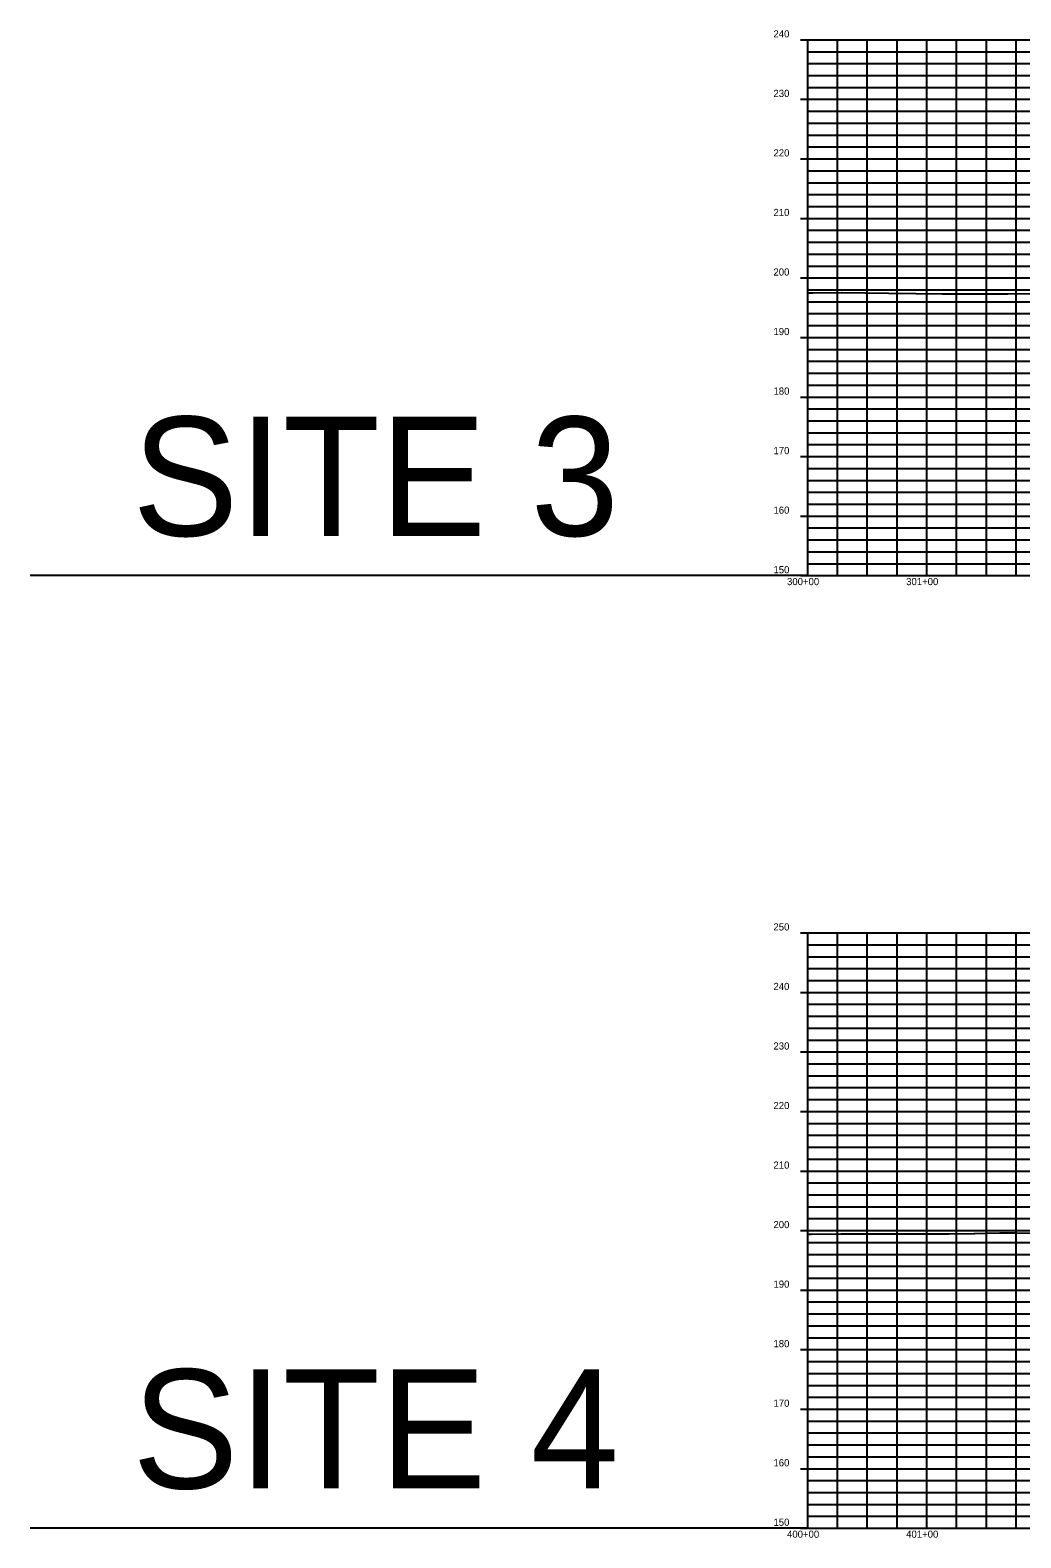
# Model space of a CAD drawing. Extents: x 1399671 to 1408349, y 1930471 to 1933387.
# Drawn here: x 1399671 to 1400503, y 1930471 to 1931737 of the extents above; entities that cross this region are included whole.
import ezdxf

# ---------------------------------------------------------------- set-up
doc = ezdxf.new("R2010")
doc.units = 0
for name, color, linetype in [('63', 7, 'Continuous'), ('8', 7, 'Continuous'), ('R_Exist Surface', 7, 'Continuous'), ('R_Grid', 7, 'Continuous'), ('R_Grid Annot', 7, 'Continuous')]:
    doc.layers.add(name, color=color, linetype=linetype)

msp = doc.modelspace()

# ---------------------------------------------------------------- linework, layer by layer
at = {"layer": '8'}
for p, q in [((1400324.2, 1931278.6), (1399671.4, 1931278.6)), ((1400324.2, 1930478.6), (1399671.4, 1930478.6))]:
    msp.add_line(p, q, dxfattribs=at)
at = {"layer": 'R_Exist Surface'}
for points in [[(1400324.2, 1931516.2), (1400328.2, 1931516.2), (1400328.8, 1931516.2), (1400352.6, 1931516.4), (1400353, 1931516.4), (1400372.3, 1931516.1), (1400372.5, 1931516.1), (1400372.8, 1931516.1), (1400392.1, 1931515.8), (1400392.3, 1931515.8), (1400414.9, 1931515.5), (1400437.1, 1931515.3), (1400437.8, 1931515.3), (1400451, 1931515.3), (1400451.4, 1931515.3), (1400464.6, 1931515.3), (1400464.9, 1931515.3), (1400478.2, 1931515.3), (1400478.5, 1931515.3), (1400478.7, 1931515.3), (1400492.1, 1931515.3), (1400492.3, 1931515.3), (1400516.2, 1931515.6)], [(1400324.2, 1930725.6), (1400324.4, 1930725.6), (1400327.1, 1930725.6), (1400327.1, 1930725.6), (1400351.9, 1930725.7), (1400352, 1930725.7), (1400352.1, 1930725.7), (1400376.7, 1930725.7), (1400376.9, 1930725.7), (1400377.2, 1930725.7), (1400393.4, 1930725.7), (1400393.8, 1930725.7), (1400409.8, 1930725.8), (1400425.7, 1930725.8), (1400426.3, 1930725.8), (1400442.1, 1930725.9), (1400442.8, 1930725.9), (1400463.6, 1930726.2), (1400464.1, 1930726.2), (1400464.6, 1930726.2), (1400485.5, 1930726.6), (1400485.6, 1930726.6), (1400495.2, 1930726.6), (1400498.3, 1930726.6), (1400511.1, 1930726.5)]]:
    msp.add_lwpolyline(points, dxfattribs=at)
at = {"layer": 'R_Grid'}
for p, q in [((1400324.2, 1931278.6), (1400324.2, 1931728.6)), ((1400324.2, 1931728.6), (1408324.2, 1931728.6)), ((1400324.2, 1931728.6), (1408324.2, 1931728.6)), ((1400349.2, 1931278.6), (1400349.2, 1931728.6)), ((1400374.2, 1931278.6), (1400374.2, 1931728.6)), ((1400399.2, 1931278.6), (1400399.2, 1931728.6)), ((1400424.2, 1931278.6), (1400424.2, 1931728.6)), ((1400449.2, 1931278.6), (1400449.2, 1931728.6)), ((1400474.2, 1931278.6), (1400474.2, 1931728.6)), ((1400499.2, 1931278.6), (1400499.2, 1931728.6)), ((1400324.2, 1931718.6), (1408324.2, 1931718.6)), ((1400324.2, 1931708.6), (1408324.2, 1931708.6)), ((1400324.2, 1931698.6), (1408324.2, 1931698.6)), ((1400324.2, 1931688.6), (1408324.2, 1931688.6)), ((1400324.2, 1931678.6), (1408324.2, 1931678.6)), ((1400324.2, 1931668.6), (1408324.2, 1931668.6)), ((1400324.2, 1931658.6), (1408324.2, 1931658.6)), ((1400324.2, 1931648.6), (1408324.2, 1931648.6)), ((1400324.2, 1931638.6), (1408324.2, 1931638.6)), ((1400324.2, 1931628.6), (1408324.2, 1931628.6)), ((1400324.2, 1931618.6), (1408324.2, 1931618.6)), ((1400324.2, 1931608.6), (1408324.2, 1931608.6)), ((1400324.2, 1931598.6), (1408324.2, 1931598.6)), ((1400324.2, 1931588.6), (1408324.2, 1931588.6)), ((1400324.2, 1931578.6), (1408324.2, 1931578.6)), ((1400324.2, 1931568.6), (1408324.2, 1931568.6)), ((1400324.2, 1931558.6), (1408324.2, 1931558.6)), ((1400324.2, 1931548.6), (1408324.2, 1931548.6)), ((1400324.2, 1931538.6), (1408324.2, 1931538.6)), ((1400324.2, 1931528.6), (1408324.2, 1931528.6)), ((1400324.2, 1931518.6), (1408324.2, 1931518.6)), ((1400324.2, 1931508.6), (1408324.2, 1931508.6)), ((1400324.2, 1931498.6), (1408324.2, 1931498.6)), ((1400324.2, 1931488.6), (1408324.2, 1931488.6)), ((1400324.2, 1931478.6), (1408324.2, 1931478.6)), ((1400324.2, 1931468.6), (1408324.2, 1931468.6)), ((1400324.2, 1931458.6), (1408324.2, 1931458.6)), ((1400324.2, 1931448.6), (1408324.2, 1931448.6)), ((1400324.2, 1931438.6), (1408324.2, 1931438.6)), ((1400324.2, 1931428.6), (1408324.2, 1931428.6)), ((1400324.2, 1931418.6), (1408324.2, 1931418.6)), ((1400324.2, 1931408.6), (1408324.2, 1931408.6)), ((1400324.2, 1931398.6), (1408324.2, 1931398.6)), ((1400324.2, 1931388.6), (1408324.2, 1931388.6)), ((1400324.2, 1931378.6), (1408324.2, 1931378.6)), ((1400324.2, 1931368.6), (1408324.2, 1931368.6)), ((1400324.2, 1931358.6), (1408324.2, 1931358.6)), ((1400324.2, 1931348.6), (1408324.2, 1931348.6)), ((1400324.2, 1931338.6), (1408324.2, 1931338.6)), ((1400324.2, 1931328.6), (1408324.2, 1931328.6)), ((1400324.2, 1931318.6), (1408324.2, 1931318.6)), ((1400324.2, 1931308.6), (1408324.2, 1931308.6)), ((1400324.2, 1931298.6), (1408324.2, 1931298.6)), ((1400324.2, 1931288.6), (1408324.2, 1931288.6)), ((1400324.2, 1931278.6), (1408324.2, 1931278.6)), ((1400324.2, 1930478.6), (1400324.2, 1930978.6)), ((1400324.2, 1930978.6), (1407124.2, 1930978.6)), ((1400324.2, 1930978.6), (1407124.2, 1930978.6)), ((1400324.2, 1930968.6), (1407124.2, 1930968.6)), ((1400349.2, 1930478.6), (1400349.2, 1930978.6)), ((1400374.2, 1930478.6), (1400374.2, 1930978.6)), ((1400399.2, 1930478.6), (1400399.2, 1930978.6)), ((1400424.2, 1930478.6), (1400424.2, 1930978.6)), ((1400449.2, 1930478.6), (1400449.2, 1930978.6)), ((1400474.2, 1930478.6), (1400474.2, 1930978.6)), ((1400499.2, 1930478.6), (1400499.2, 1930978.6)), ((1400324.2, 1930958.6), (1407124.2, 1930958.6)), ((1400324.2, 1930948.6), (1407124.2, 1930948.6)), ((1400324.2, 1930938.6), (1407124.2, 1930938.6)), ((1400324.2, 1930928.6), (1407124.2, 1930928.6)), ((1400324.2, 1930918.6), (1407124.2, 1930918.6)), ((1400324.2, 1930908.6), (1407124.2, 1930908.6)), ((1400324.2, 1930898.6), (1407124.2, 1930898.6)), ((1400324.2, 1930888.6), (1407124.2, 1930888.6)), ((1400324.2, 1930878.6), (1407124.2, 1930878.6)), ((1400324.2, 1930868.6), (1407124.2, 1930868.6)), ((1400324.2, 1930858.6), (1407124.2, 1930858.6)), ((1400324.2, 1930848.6), (1407124.2, 1930848.6)), ((1400324.2, 1930838.6), (1407124.2, 1930838.6)), ((1400324.2, 1930828.6), (1407124.2, 1930828.6)), ((1400324.2, 1930818.6), (1407124.2, 1930818.6)), ((1400324.2, 1930808.6), (1407124.2, 1930808.6)), ((1400324.2, 1930798.6), (1407124.2, 1930798.6)), ((1400324.2, 1930788.6), (1407124.2, 1930788.6)), ((1400324.2, 1930778.6), (1407124.2, 1930778.6)), ((1400324.2, 1930768.6), (1407124.2, 1930768.6)), ((1400324.2, 1930758.6), (1407124.2, 1930758.6)), ((1400324.2, 1930748.6), (1407124.2, 1930748.6)), ((1400324.2, 1930738.6), (1407124.2, 1930738.6)), ((1400324.2, 1930728.6), (1407124.2, 1930728.6)), ((1400324.2, 1930718.6), (1407124.2, 1930718.6)), ((1400324.2, 1930708.6), (1407124.2, 1930708.6)), ((1400324.2, 1930698.6), (1407124.2, 1930698.6)), ((1400324.2, 1930688.6), (1407124.2, 1930688.6)), ((1400324.2, 1930678.6), (1407124.2, 1930678.6)), ((1400324.2, 1930668.6), (1407124.2, 1930668.6)), ((1400324.2, 1930658.6), (1407124.2, 1930658.6)), ((1400324.2, 1930648.6), (1407124.2, 1930648.6)), ((1400324.2, 1930638.6), (1407124.2, 1930638.6)), ((1400324.2, 1930628.6), (1407124.2, 1930628.6)), ((1400324.2, 1930618.6), (1407124.2, 1930618.6)), ((1400324.2, 1930608.6), (1407124.2, 1930608.6)), ((1400324.2, 1930598.6), (1407124.2, 1930598.6)), ((1400324.2, 1930588.6), (1407124.2, 1930588.6)), ((1400324.2, 1930578.6), (1407124.2, 1930578.6)), ((1400324.2, 1930568.6), (1407124.2, 1930568.6)), ((1400324.2, 1930558.6), (1407124.2, 1930558.6)), ((1400324.2, 1930548.6), (1407124.2, 1930548.6)), ((1400324.2, 1930538.6), (1407124.2, 1930538.6)), ((1400324.2, 1930528.6), (1407124.2, 1930528.6)), ((1400324.2, 1930518.6), (1407124.2, 1930518.6)), ((1400324.2, 1930508.6), (1407124.2, 1930508.6)), ((1400324.2, 1930498.6), (1407124.2, 1930498.6)), ((1400324.2, 1930488.6), (1407124.2, 1930488.6)), ((1400324.2, 1930478.6), (1407124.2, 1930478.6))]:
    msp.add_line(p, q, dxfattribs=at)
at = {"layer": 'R_Grid Annot'}
for p, q in [((1400318.2, 1931728.6), (1400324.2, 1931728.6)), ((1400318.2, 1931728.6), (1400324.2, 1931728.6)), ((1400324.2, 1931718.6), (1400327.2, 1931718.6)), ((1400324.2, 1931708.6), (1400327.2, 1931708.6)), ((1400324.2, 1931698.6), (1400327.2, 1931698.6)), ((1400318.2, 1931678.6), (1400324.2, 1931678.6)), ((1400324.2, 1931688.6), (1400327.2, 1931688.6)), ((1400324.2, 1931668.6), (1400327.2, 1931668.6)), ((1400324.2, 1931658.6), (1400327.2, 1931658.6)), ((1400324.2, 1931648.6), (1400327.2, 1931648.6)), ((1400324.2, 1931638.6), (1400327.2, 1931638.6)), ((1400318.2, 1931628.6), (1400324.2, 1931628.6)), ((1400324.2, 1931618.6), (1400327.2, 1931618.6)), ((1400324.2, 1931608.6), (1400327.2, 1931608.6)), ((1400324.2, 1931598.6), (1400327.2, 1931598.6)), ((1400324.2, 1931588.6), (1400327.2, 1931588.6)), ((1400318.2, 1931578.6), (1400324.2, 1931578.6)), ((1400324.2, 1931568.6), (1400327.2, 1931568.6)), ((1400324.2, 1931558.6), (1400327.2, 1931558.6)), ((1400324.2, 1931548.6), (1400327.2, 1931548.6)), ((1400324.2, 1931538.6), (1400327.2, 1931538.6)), ((1400318.2, 1931528.6), (1400324.2, 1931528.6)), ((1400324.2, 1931518.6), (1400327.2, 1931518.6)), ((1400324.2, 1931508.6), (1400327.2, 1931508.6)), ((1400324.2, 1931498.6), (1400327.2, 1931498.6)), ((1400324.2, 1931488.6), (1400327.2, 1931488.6)), ((1400318.2, 1931478.6), (1400324.2, 1931478.6)), ((1400324.2, 1931468.6), (1400327.2, 1931468.6)), ((1400324.2, 1931458.6), (1400327.2, 1931458.6)), ((1400324.2, 1931448.6), (1400327.2, 1931448.6)), ((1400324.2, 1931438.6), (1400327.2, 1931438.6)), ((1400318.2, 1931428.6), (1400324.2, 1931428.6)), ((1400324.2, 1931418.6), (1400327.2, 1931418.6)), ((1400324.2, 1931408.6), (1400327.2, 1931408.6)), ((1400324.2, 1931398.6), (1400327.2, 1931398.6)), ((1400324.2, 1931388.6), (1400327.2, 1931388.6)), ((1400318.2, 1931378.6), (1400324.2, 1931378.6)), ((1400324.2, 1931368.6), (1400327.2, 1931368.6)), ((1400324.2, 1931358.6), (1400327.2, 1931358.6)), ((1400324.2, 1931348.6), (1400327.2, 1931348.6)), ((1400324.2, 1931338.6), (1400327.2, 1931338.6)), ((1400318.2, 1931328.6), (1400324.2, 1931328.6)), ((1400324.2, 1931318.6), (1400327.2, 1931318.6)), ((1400324.2, 1931308.6), (1400327.2, 1931308.6)), ((1400324.2, 1931298.6), (1400327.2, 1931298.6)), ((1400324.2, 1931288.6), (1400327.2, 1931288.6)), ((1400318.2, 1931278.6), (1400324.2, 1931278.6)), ((1400318.2, 1930978.6), (1400324.2, 1930978.6)), ((1400318.2, 1930978.6), (1400324.2, 1930978.6)), ((1400324.2, 1930968.6), (1400327.2, 1930968.6)), ((1400324.2, 1930958.6), (1400327.2, 1930958.6)), ((1400324.2, 1930948.6), (1400327.2, 1930948.6)), ((1400324.2, 1930938.6), (1400327.2, 1930938.6)), ((1400318.2, 1930928.6), (1400324.2, 1930928.6)), ((1400324.2, 1930918.6), (1400327.2, 1930918.6)), ((1400324.2, 1930908.6), (1400327.2, 1930908.6)), ((1400324.2, 1930898.6), (1400327.2, 1930898.6)), ((1400318.2, 1930878.6), (1400324.2, 1930878.6)), ((1400324.2, 1930888.6), (1400327.2, 1930888.6)), ((1400324.2, 1930868.6), (1400327.2, 1930868.6)), ((1400324.2, 1930858.6), (1400327.2, 1930858.6)), ((1400324.2, 1930848.6), (1400327.2, 1930848.6)), ((1400318.2, 1930828.6), (1400324.2, 1930828.6)), ((1400324.2, 1930838.6), (1400327.2, 1930838.6)), ((1400324.2, 1930818.6), (1400327.2, 1930818.6)), ((1400324.2, 1930808.6), (1400327.2, 1930808.6)), ((1400324.2, 1930798.6), (1400327.2, 1930798.6)), ((1400318.2, 1930778.6), (1400324.2, 1930778.6)), ((1400324.2, 1930788.6), (1400327.2, 1930788.6)), ((1400324.2, 1930768.6), (1400327.2, 1930768.6)), ((1400324.2, 1930758.6), (1400327.2, 1930758.6)), ((1400324.2, 1930748.6), (1400327.2, 1930748.6)), ((1400318.2, 1930728.6), (1400324.2, 1930728.6)), ((1400324.2, 1930738.6), (1400327.2, 1930738.6)), ((1400324.2, 1930718.6), (1400327.2, 1930718.6)), ((1400324.2, 1930708.6), (1400327.2, 1930708.6)), ((1400324.2, 1930698.6), (1400327.2, 1930698.6)), ((1400324.2, 1930688.6), (1400327.2, 1930688.6)), ((1400318.2, 1930678.6), (1400324.2, 1930678.6)), ((1400324.2, 1930668.6), (1400327.2, 1930668.6)), ((1400324.2, 1930658.6), (1400327.2, 1930658.6)), ((1400324.2, 1930648.6), (1400327.2, 1930648.6)), ((1400324.2, 1930638.6), (1400327.2, 1930638.6)), ((1400318.2, 1930628.6), (1400324.2, 1930628.6)), ((1400324.2, 1930618.6), (1400327.2, 1930618.6)), ((1400324.2, 1930608.6), (1400327.2, 1930608.6)), ((1400324.2, 1930598.6), (1400327.2, 1930598.6)), ((1400324.2, 1930588.6), (1400327.2, 1930588.6)), ((1400318.2, 1930578.6), (1400324.2, 1930578.6)), ((1400324.2, 1930568.6), (1400327.2, 1930568.6)), ((1400324.2, 1930558.6), (1400327.2, 1930558.6)), ((1400324.2, 1930548.6), (1400327.2, 1930548.6)), ((1400324.2, 1930538.6), (1400327.2, 1930538.6)), ((1400318.2, 1930528.6), (1400324.2, 1930528.6)), ((1400324.2, 1930518.6), (1400327.2, 1930518.6)), ((1400324.2, 1930508.6), (1400327.2, 1930508.6)), ((1400324.2, 1930498.6), (1400327.2, 1930498.6)), ((1400324.2, 1930488.6), (1400327.2, 1930488.6)), ((1400318.2, 1930478.6), (1400324.2, 1930478.6))]:
    msp.add_line(p, q, dxfattribs=at)

# ---------------------------------------------------------------- texts
at = {"layer": '63'}
for p in [(1400324.2, 1931278.6), (1400324.2, 1930478.6)]:
    msp.add_text('-', height=0.0001, dxfattribs=at).set_placement(p)
at = {"layer": '8'}
for s, p in [('SITE 3', (1399757.1, 1931312)), ('SITE 4', (1399757.1, 1930512))]:
    msp.add_text(s, height=100, dxfattribs=at).set_placement(p)
at = {"layer": 'R_Grid Annot'}
for s, p in [('240', (1400295.4, 1931730.6)), ('240', (1400295.4, 1931730.6)), ('230', (1400295.4, 1931680.6)), ('220', (1400295.4, 1931630.6)), ('210', (1400295.4, 1931580.6)), ('200', (1400295.4, 1931530.6)), ('190', (1400295.4, 1931480.6)), ('180', (1400295.4, 1931430.6)), ('170', (1400295.4, 1931380.6)), ('160', (1400295.4, 1931330.6)), ('150', (1400295.4, 1931280.6)), ('300+00', (1400306.8, 1931270.6)), ('301+00', (1400406.8, 1931270.6)), ('250', (1400295.4, 1930980.6)), ('250', (1400295.4, 1930980.6)), ('240', (1400295.4, 1930930.6)), ('230', (1400295.4, 1930880.6)), ('220', (1400295.4, 1930830.6)), ('210', (1400295.4, 1930780.6)), ('200', (1400295.4, 1930730.6)), ('190', (1400295.4, 1930680.6)), ('180', (1400295.4, 1930630.6)), ('170', (1400295.4, 1930580.6)), ('160', (1400295.4, 1930530.6)), ('150', (1400295.4, 1930480.6)), ('400+00', (1400306.8, 1930470.6)), ('401+00', (1400406.8, 1930470.6))]:
    msp.add_text(s, height=6, dxfattribs=at).set_placement(p)

doc.saveas('drawing.dxf')
